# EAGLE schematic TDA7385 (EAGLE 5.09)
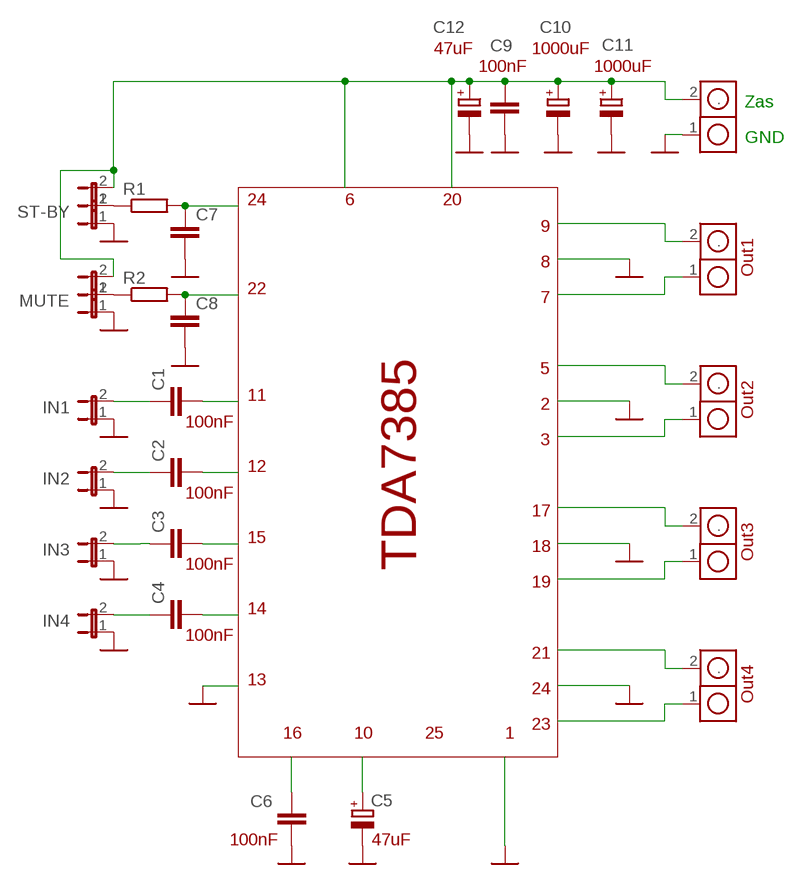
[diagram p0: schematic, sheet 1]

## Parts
C1  C-EU050-025X075  [C050-025X075]
C2  C-EU050-025X075  [C050-025X075]
C3  C-EU050-025X075  [C050-025X075]
C4  C-EU050-025X075  [C050-025X075]
C5  CPOL-EUE2.5-6  [E2,5-6]
C6  C-EU050-025X075  [C050-025X075]
C7  C-EU050-050X075  [C050-050X075]
C8  C-EU050-050X075  [C050-050X075]
C9  C-EU050-025X075  [C050-025X075]
C10  CPOL-EUE5-10.5  [E5-10,5]
C11  CPOL-EUE5-10.5  [E5-10,5]
C12  CPOL-EUE2.5-6  [E2,5-6]
IN1  JP1E  [JP1]
IN2  JP1E  [JP1]
IN3  JP1E  [JP1]
IN4  JP1E  [JP1]
MUTE  JP1E  [JP1]
MUTE1  JP1E  [JP1]
R1  R-EU_0207/10  [0207/10]
R2  R-EU_0207/10  [0207/10]
ST-BY  JP1E  [JP1]
ST-BY1  JP1E  [JP1]
U$1  ARK2  [ARK2]
U$2  ARK2  [ARK2]
U$3  ARK2  [ARK2]
U$4  ARK2  [ARK2]
U$9  ARK2  [ARK2]

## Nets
GND: C5.- C6.1 C7.2 C8.2 C9.1 C10.- C11.- C12.- IN1.1 IN2.1 IN3.1 IN4.1 MUTE.1 ST-BY.1 U$9.1
N$1: U$1.2(.)
N$2: U$1.1
N$3: U$2.2(.)
N$4: U$2.1
N$5: U$3.2(.)
N$6: U$3.1
N$7: U$4.2(.)
N$8: U$4.1
N$9: C5.+
N$10: C6.2
N$11: C4.2
N$12: C3.2
N$13: C2.2
N$14: C1.2
N$15: C1.1 IN1.2
N$16: C7.1 R1.2
N$17: C8.1 R2.2
N$19: C2.1 IN2.2
N$20: C3.1 IN3.2
N$21: C4.1 IN4.2
N$22: C9.2 C10.+ C11.+ C12.+ MUTE1.2 ST-BY1.2 U$9.2(.)
N$23: R1.1 ST-BY1.1 ST-BY.2
N$24: MUTE1.1 MUTE.2 R2.1

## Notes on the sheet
- 47uF | 1000uF
- 100nF | 1000uF
- Zas
- GND
- 24 | 6 | 20
- 9
- 8
- Out1
- 22
- 7
- 5
- 11
- 2
- Out2
- 100nF
- 3
- 12
- 100nF
- 17
- 15
- 18
- Out3
- 100nF | TDA7385
- 19
- 14
- 100nF
- 21
- 13
- 24
- Out4
- 23
- 16 | 10 | 25 | 1
- 100nF | 47uF

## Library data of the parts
C1-C4 C6-C9 = rcl:C-EU: CAPACITOR, European symbol
C5 C10-C12 = rcl:CPOL-EU: POLARIZED CAPACITOR, European symbol
IN1-IN4 MUTE MUTE1 ST-BY ST-BY1 = jumper:JP1E: JUMPER
R1 R2 = rcl:R-EU_: RESISTOR, European symbol
U$1-U$4 U$9 = ark2:ARK2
